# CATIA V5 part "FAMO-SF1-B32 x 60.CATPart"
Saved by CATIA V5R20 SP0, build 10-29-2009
Part number: FAMO-SF1-B32 x 60
Definition: NONE
Nomenclature: FAMO-SF1-B32 x 60
Source: Unknown
Description: FAMO-SF1-B32 x 60
Bounding box of the stored display mesh (mm): x -13 to 47, y -26.5 to 26.5, z -26.5 to 26.5
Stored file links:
  C:\Users\Utente\Desktop\IO LAVORO\3D X SITO CF\X SITO\FAMO\FAMO-SF1-B32 x 60.CATPart
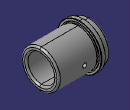
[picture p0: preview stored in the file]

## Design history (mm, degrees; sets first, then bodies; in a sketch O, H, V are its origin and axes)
Body1 "FAMO-SF1-B32 x 60" (main body)
  Solid1: solid without history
